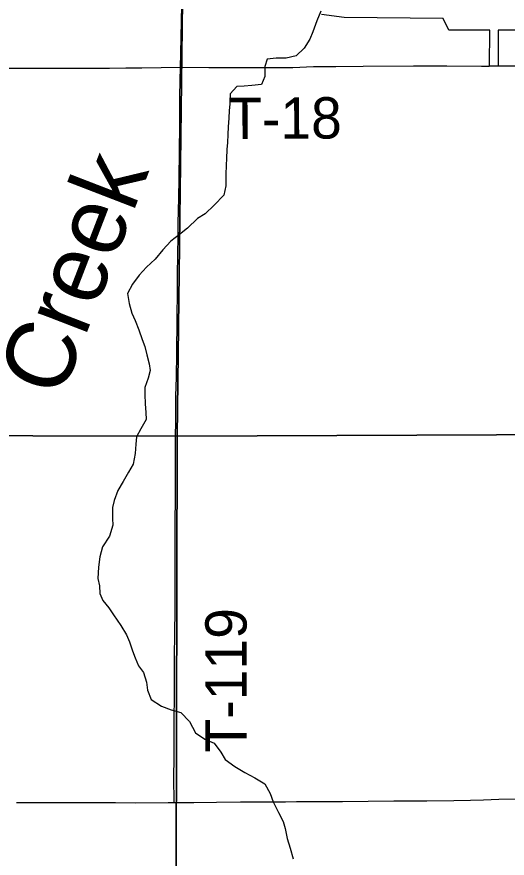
# Model space of a CAD drawing. Extents: x 0 to 34, y 0 to 22.
# Drawn here: x 4.352 to 4.689, y 17.617 to 18.195 of the extents above; entities that cross this region are included whole.
import ezdxf

# ---------------------------------------------------------------- set-up
doc = ezdxf.new("R2010")
doc.units = 0
for name, color, linetype in [('GM_X_Corporation', 7, 'Continuous'), ('GM_X_County_Road', 7, 'Continuous'), ('GM_X_Minor_River', 7, 'Continuous'), ('GM_X_Minor_River_Text', 7, 'Continuous'), ('GM_X_Section', 7, 'Continuous'), ('GM_X_Township_Road', 7, 'Continuous'), ('GM_X_Township_Road_Text', 7, 'Continuous')]:
    doc.layers.add(name, color=color, linetype=linetype)

msp = doc.modelspace()

# ---------------------------------------------------------------- linework, layer by layer
at = {"layer": 'GM_X_Corporation'}
msp.add_lwpolyline([(4.71227, 18.20866), (4.71197, 18.18573), (4.68267, 18.18572), (4.68275, 18.1612), (4.67681, 18.16118), (4.67699, 18.18572), (4.65347, 18.18572), (4.64881, 18.18572), (4.64491, 18.19393), (4.57691, 18.19456), (4.56139, 18.19654)], dxfattribs=at)
at = {"layer": 'GM_X_County_Road'}
for points in [[(4.46428, 18.1603), (4.46451, 18.16997), (4.46555, 18.21408), (4.46644, 18.25212), (4.4676, 18.30134), (4.4686, 18.34398), (4.46864, 18.36173), (4.4686, 18.36356), (4.46846, 18.36513), (4.46824, 18.36681), (4.46782, 18.36829)], [(4.34312, 18.15975), (4.35243, 18.15978), (4.3717, 18.15966), (4.3832, 18.15961), (4.39719, 18.15973), (4.40588, 18.15973), (4.41552, 18.1598), (4.42671, 18.15983), (4.43789, 18.15985), (4.46428, 18.1603)], [(4.35172, 17.655), (4.36882, 17.65505), (4.39586, 17.65498), (4.40984, 17.65498), (4.41978, 17.65491), (4.43315, 17.6549), (4.45583, 17.65499), (4.46005, 17.65502)], [(4.46005, 17.65502), (4.47354, 17.6551), (4.48908, 17.65527), (4.50555, 17.65537), (4.52157, 17.65548)], [(4.52157, 17.65548), (4.52295, 17.65549), (4.53658, 17.65557)], [(4.53658, 17.65557), (4.54409, 17.65561), (4.57578, 17.65563), (4.6109, 17.65611), (4.63359, 17.65622), (4.65223, 17.65643), (4.66372, 17.65656), (4.67272, 17.65687), (4.68328, 17.65733), (4.6948, 17.65745)]]:
    msp.add_lwpolyline(points, dxfattribs=at)
at = {"layer": 'GM_X_Minor_River'}
for points in [[(4.56092, 18.19893), (4.55803, 18.19231), (4.55532, 18.18474), (4.55338, 18.17964), (4.54936, 18.1734), (4.54381, 18.16813), (4.53697, 18.16648), (4.53014, 18.16653), (4.52388, 18.16581), (4.52232, 18.16089), (4.52227, 18.15387), (4.51996, 18.14858), (4.5135, 18.14768), (4.50818, 18.14734), (4.50306, 18.14719), (4.49847, 18.1421), (4.49843, 18.13716), (4.49782, 18.13053), (4.49759, 18.12522), (4.49717, 18.11934), (4.49694, 18.11422), (4.49671, 18.10872), (4.4963, 18.10379), (4.49606, 18.09772), (4.49584, 18.09297), (4.4956, 18.08652), (4.49554, 18.07875), (4.49417, 18.07249), (4.48748, 18.06552), (4.48137, 18.05969), (4.47603, 18.05631), (4.46915, 18.04972), (4.46362, 18.0454), (4.4577, 18.04089), (4.45216, 18.03486), (4.44699, 18.02845), (4.44107, 18.02299), (4.4359, 18.01733), (4.43131, 18.0113), (4.42803, 18.00487), (4.42912, 17.99803), (4.43097, 17.99138), (4.43321, 17.98624), (4.43582, 17.97996), (4.43805, 17.97311), (4.43991, 17.96835), (4.4412, 17.96265), (4.44286, 17.95657), (4.4434, 17.95182), (4.44203, 17.94671), (4.4399, 17.94027), (4.43986, 17.93553), (4.44001, 17.92907), (4.44053, 17.923), (4.44069, 17.91825), (4.43704, 17.91183), (4.43415, 17.90635), (4.43373, 17.90123), (4.43331, 17.89478)], [(4.43331, 17.89478), (4.43193, 17.88758), (4.42866, 17.8821), (4.42501, 17.87568), (4.42136, 17.86944), (4.41885, 17.86263), (4.41767, 17.85771), (4.41762, 17.85031), (4.41777, 17.84556), (4.41563, 17.83799), (4.41065, 17.83082), (4.40889, 17.82381), (4.40789, 17.8168), (4.40764, 17.80902), (4.40874, 17.80389), (4.40889, 17.79858), (4.41095, 17.79382), (4.41509, 17.78885), (4.41828, 17.7839), (4.42335, 17.77665), (4.42729, 17.77036), (4.42934, 17.76541), (4.43138, 17.75932), (4.43324, 17.75437), (4.43548, 17.74904), (4.43886, 17.74427), (4.4409, 17.73762), (4.44162, 17.73211), (4.44423, 17.72583), (4.45121, 17.72122), (4.45784, 17.71871), (4.46465, 17.71676), (4.47049, 17.71065), (4.47461, 17.70283), (4.48103, 17.69861), (4.48746, 17.69572), (4.49216, 17.68961), (4.49516, 17.68466), (4.50176, 17.67967), (4.50856, 17.67564), (4.51537, 17.67198), (4.52236, 17.66795), (4.52591, 17.66128), (4.52815, 17.65557), (4.5317, 17.64814), (4.53488, 17.64205), (4.53636, 17.6371), (4.53764, 17.63026), (4.53968, 17.62361), (4.54171, 17.61638)]]:
    msp.add_lwpolyline(points, dxfattribs=at)
at = {"layer": 'GM_X_Section'}
for points in [[(4.46827, 18.41225), (4.46218, 17.9068), (3.96579, 17.90789), (3.9728, 18.4103)], [(4.95692, 18.41406), (4.95614, 17.90875), (4.46218, 17.9068), (4.46827, 18.41225)], [(3.96579, 17.90789), (4.46218, 17.9068), (4.46085, 17.40415), (4.45706, 17.40418), (3.97319, 17.40651), (3.95917, 17.40642)], [(4.46218, 17.9068), (4.95614, 17.90875), (4.96051, 17.40814), (4.95501, 17.40799), (4.46085, 17.40415)]]:
    msp.add_lwpolyline(points, close=True, dxfattribs=at)
at = {"layer": 'GM_X_Township_Road'}
for points in [[(4.46011, 17.70473), (4.4601, 17.70856), (4.46008, 17.71308), (4.46015, 17.72707), (4.46032, 17.73919), (4.46033, 17.75504), (4.46047, 17.7712), (4.46061, 17.78736), (4.46063, 17.80259), (4.46065, 17.81067), (4.46068, 17.81657), (4.46071, 17.82433), (4.46075, 17.83024), (4.46073, 17.83458), (4.46074, 17.84981), (4.46082, 17.86193), (4.46086, 17.87001), (4.46091, 17.87373), (4.46099, 17.8852), (4.46098, 17.89234), (4.461, 17.90102), (4.46104, 17.90909), (4.46113, 17.91438), (4.46118, 17.92028), (4.46119, 17.92711), (4.46126, 17.93426), (4.46153, 17.94731), (4.46177, 17.96379), (4.4619, 17.97093), (4.46201, 17.97994), (4.46209, 17.98802), (4.46212, 17.9902), (4.46217, 17.99548), (4.46221, 17.99921), (4.46228, 18.00698), (4.46235, 18.0166), (4.46252, 18.03245), (4.46269, 18.04302), (4.46286, 18.05327), (4.46318, 18.07036), (4.46342, 18.08403), (4.46387, 18.1207), (4.46394, 18.13998), (4.46411, 18.15117), (4.46428, 18.1603)], [(4.46428, 18.1603), (4.48388, 18.16026), (4.52259, 18.16009), (4.54161, 18.16026), (4.55582, 18.16073), (4.57103, 18.16076), (4.58998, 18.16102), (4.62447, 18.16127), (4.63657, 18.16132), (4.64741, 18.1614), (4.67131, 18.16116), (4.67644, 18.16118)], [(4.67644, 18.16118), (4.68199, 18.16121)], [(4.68199, 18.16121), (4.70945, 18.16133), (4.72243, 18.16137), (4.73524, 18.16152)], [(4.46005, 17.65502), (4.46, 17.65899), (4.45988, 17.66864), (4.46006, 17.68946), (4.46008, 17.69661), (4.46009, 17.70047), (4.46011, 17.70473)]]:
    msp.add_lwpolyline(points, dxfattribs=at)

# ---------------------------------------------------------------- texts
at = {"layer": 'GM_X_Minor_River_Text'}
msp.add_text('Creek', height=0.047373, rotation=68.89261, dxfattribs=at).set_placement((4.38211, 17.93157))
at = {"layer": 'GM_X_Township_Road_Text'}
for s, rotation, p in [('T-18', 0.3528, (4.49721, 18.11091)), ('T-119', 90, (4.5098, 17.68938))]:
    msp.add_text(s, height=0.028409, rotation=rotation, dxfattribs=at).set_placement(p)

doc.saveas('drawing.dxf')
